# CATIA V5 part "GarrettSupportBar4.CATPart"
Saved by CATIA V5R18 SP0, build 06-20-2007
Part number: NLG-10020-1
Bounding box of the stored display mesh (mm): x -25.4 to 912.519, y -139.7 to 139.7, z -50.787 to 50.787
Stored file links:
  \\william7-64\echange\4Gavin\iPad\new.CATPart
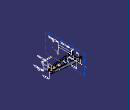
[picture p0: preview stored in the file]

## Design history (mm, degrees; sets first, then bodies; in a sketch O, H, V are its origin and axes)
AxisSystem1 "Absolute Axis System": origin (0, 0, 0), X (1, 0, 0), Y (0, 1, 0), Z (0, 0, 1)
TTRSSet1
f4a2d38f3ddc11d3a929006094b99c4b_11 "CATTPSSet"
Set1 "DATUM PLANES"
  Plane1 "DATUM A": type Offset, RefPlane start face of Pocket2, Offset 0, reversed
  Plane2 "DATUM B": type Offset, RefPlane face of Pad1 from Sketch1.L9, Offset 0, reversed
  Plane3 "DATUM C": type Offset, RefPlane face of Pad1 from Sketch1.L8, Offset 0, reversed
Body1 (main body)
  Sketch1 on face of AxisSystem1, origin (0, 0, 0), H (1, 0, 0), V (0, 1, 0)
    line L1 (912.9878, 76.2) -> (912.9878, 50.8)
    point P1 (912.9878, 76.2)
    point P2 (912.9878, -76.2)
    line L2 (-25.4, -139.7) -> (127, -139.7)
    point P3 (127, -139.7)
    line L3 (127, -139.7) -> (810.8024, -76.2543)
    line L4 (811.9757, -76.2) -> (912.9878, -76.2)
    point P4 (912.9878, 76.2)
    point P5 (811.3878, 76.2)
    line L5 (811.9757, 76.2) -> (912.9878, 76.2)
    point P6 (127, 139.7)
    line L6 (127.5854, 139.6457) -> (810.8024, 76.2543)
    point P7 (-25.4, 139.7)
    line L7 (-25.4, 139.7) -> (126.4121, 139.7)
    line L8 (-25.4, 114.3) -> (88.9, 114.3)
    line L9 (101.6, 101.6) -> (101.6, -101.6)
    line L10 (88.9, -114.3) -> (-25.4, -114.3)
    point P8 (101.6, 114.3)
    point P9 (101.6, -114.3)
    line L11 (-25.4, 139.7) -> (-25.4, 114.3)
    reference intersected line E1 through (0, 0) direction (-1, 0) from face of AxisSystem1
    line L12 (-25.4, -114.3) -> (-25.4, -139.7)
    line L13 (912.9878, 50.8) -> (849.4878, 50.8)
    line L14 (836.7878, 38.1) -> (836.7878, -38.1)
    line L15 (849.4878, -50.8) -> (912.9878, -50.8)
    line L16 (912.9878, -50.8) -> (912.9878, -76.2)
    arc A1 centre (811.9757, -88.9) radius 12.7 from (810.8024, -76.2543) to (811.9757, -76.2) cw
    arc A2 centre (811.9757, 88.9) radius 12.7 from (811.9757, 76.2) to (810.8024, 76.2543) cw
    arc A3 centre (126.4121, 127) radius 12.7 from (127.5854, 139.6457) to (126.4121, 139.7) ccw
    arc A4 centre (88.9, 101.6) radius 12.7 from (88.9, 114.3) to (101.6, 101.6) cw
    arc A5 centre (88.9, -101.6) radius 12.7 from (101.6, -101.6) to (88.9, -114.3) cw
    arc A6 centre (849.4878, 38.1) radius 12.7 from (849.4878, 50.8) to (836.7878, 38.1) ccw
    arc A7 centre (849.4878, -38.1) radius 12.7 from (836.7878, -38.1) to (849.4878, -50.8) ccw
    circle A8 centre (285.4046, 0) radius 73.668
    point P36 (285.4046, 0)
    circle A9 centre (469.199, 0) radius 56.6878
    point P37 (469.199, 0)
    point P38 (525.8868, 0)
    circle A10 centre (652.9934, 0) radius 39.7077
    point P39 (652.9934, 0)
    point P40 (692.7011, 0)
    distance P1 H = 76.2
    distance L10 L2 = 25.4
    distance E1 L7 = 139.7
    distance L11 L9 = 127
    distance P1 P2 = 152.4
    distance L13 L5 = 25.4
    distance L15 L4 = 25.4
    distance L1 L14 = 76.2
    radius A1 = 12.7
    distance P5 P4 = 101.6
    radius A2 = 12.7 {= Sketch1.radius(A1)}
    distance P7 P6 = 152.4
    radius A3 = 12.7 {= Sketch1.radius(A1)}
    distance P8 P9 = 228.6
    radius A4 = 12.7 {= Sketch1.radius(A1)}
    radius A5 = 12.7 {= Sketch1.radius(A1)}
    radius A6 = 12.7 {= Sketch1.radius(A1)}
    radius A7 = 12.7 {= Sketch1.radius(A1)}
    distance L9 L14 = 735.1878
    distance L14 P39 = 183.7944
    distance P39 P37 = 183.7944 {= Sketch1.distance(L14 P39)}
    distance P37 P36 = 183.7944 {= Sketch1.distance(L14 P39)}
    distance P36 L9 = 183.8046 (reference)
    distance A8 L6 = 50.8
    distance A9 L6 = 50.8
    distance A10 L6 = 50.8
    vertical: L1 V, L9 V, L11 V, L14 V
    horizontal: L2 H, L4 H, L8 H, L10 H, L13 H, L15 H
    symmetry: P2 P4 H, L4 L5 H, P3 P6 H, L3 L6 H, L2 L7 H
    coincidence: L11 L12, L1 L16, L5 P5, L6 P5, L6 P6, L7 P6, L8 P8, L9 P8, L9 P9, L10 P9, P36 H, P37 H, A9 P38, P38 H, P39 H, A10 P40, P40 H
    tangency: A1 L3, A1 L4, A2 L5, A2 L6, A3 L6, A3 L7, A4 L8, A4 L9, A5 L9, A5 L10, A6 L13, A6 L14, A7 L14, A7 L15
  Pad1: profile Sketch1, direction (0, 0, 1), length 50.8, mirrored extent
  Sketch2 on face of Pad1, origin (0, -139.7, 0), H (1, 0, 0), V (0, 0, 1)
    arc A1 centre (881.2378, 0) radius 31.75 from (881.9445, -31.7421) to (881.9445, 31.7421) ccw
    point P1 (881.2378, 0)
    arc A2 centre (25.4, 0) radius 50.8 from (26.5308, 50.7874) to (26.5308, -50.7874) ccw
    point P2 (25.4, 0)
    reference projected line E1 (912.9878, -50.8) -> (912.9878, 50.8) from edge [face of Pad1 | face of Pad1]
    reference projected line E2 (-25.4, -50.8) -> (-25.4, 50.8) from edge [face of Pad1 | face of Pad1]
    line L1 (26.5308, 50.7874) -> (881.9445, 31.7421)
    line L2 (881.9445, -31.7421) -> (26.5308, -50.7874)
    line L3 (-110, 130) -> (970, 130)
    line L4 (970, 130) -> (970, -130)
    line L5 (970, -130) -> (-110, -130)
    line L6 (-110, -130) -> (-110, 130)
    circle A3 centre (25.4, 0) radius 31.75
    circle A4 centre (881.2378, 0) radius 19.05
    radius A1 = 31.75
    radius A2 = 50.8
    radius A3 = 31.75
    radius A4 = 19.05
    coincidence: P1 H, P2 H
    tangency: A1 E1, A2 E2, L1 A2, L1 A1, L2 A1, L2 A2
    horizontal: L3 H, L5 H
    vertical: L4 V, L6 V
  Pocket1: profile Sketch2, direction (0, 1, 0), through (limit type 3)
  Sketch3 on face of AxisSystem1, origin (0, 0, 0), H (1, 0, 0), V (0, 1, 0)
    offset line E1 (140.8733, 112.9037) -> (799.8611, 51.7604) from edge [face of Pocket1 | face of Pad1]
    offset line E2 (811.3878, 39.1147) -> (811.3878, -39.1147) from edge [face of Pocket1 | face of Pad1]
    offset line E3 (140.8733, -112.9037) -> (799.8611, -51.7604) from edge [face of Pad1 | face of Pocket1]
    offset line E4 (127, -100.258) -> (127, 100.258) from edge [face of Pocket1 | face of Pad1]
    arc A1 centre (798.6878, 39.1147) radius 12.7 from (799.8611, 51.7604) to (811.3878, 39.1147) cw
    arc A2 centre (798.6878, -39.1147) radius 12.7 from (811.3878, -39.1147) to (799.8611, -51.7604) cw
    arc A3 centre (139.7, 100.258) radius 12.7 from (140.8733, 112.9037) to (127, 100.258) ccw
    arc A4 centre (139.7, -100.258) radius 12.7 from (140.8733, -112.9037) to (127, -100.258) cw
    radius A1 = 12.7
    radius A2 = 12.7
    radius A3 = 12.7
    radius A4 = 12.7
    tangency: A1 E1, A1 E2, A2 E2, A2 E3, A3 E1, A3 E4, A4 E3, A4 E4
  Pocket2: profile Sketch3, direction (0, 0, -1), through (limit type 3), opposite side length -6.35
  Sketch4 on face of AxisSystem1, origin (0, 0, 0), H (1, 0, 0), V (0, 1, 0)
    offset line E1 (140.8733, 112.9037) -> (799.8611, 51.7604) from edge [face of Pocket1 | face of Pad1]
    offset line E2 (811.3878, 39.1147) -> (811.3878, -39.1147) from edge [face of Pocket1 | face of Pad1]
    offset line E3 (140.8733, -112.9037) -> (799.8611, -51.7604) from edge [face of Pad1 | face of Pocket1]
    offset line E4 (127, -100.258) -> (127, 100.258) from edge [face of Pocket1 | face of Pad1]
    arc A1 centre (798.6878, 39.1147) radius 12.7 from (799.8611, 51.7604) to (811.3878, 39.1147) cw
    arc A2 centre (798.6878, -39.1147) radius 12.7 from (811.3878, -39.1147) to (799.8611, -51.7604) cw
    arc A3 centre (139.7, -100.258) radius 12.7 from (127, -100.258) to (140.8733, -112.9037) ccw
    arc A4 centre (139.7, 100.258) radius 12.7 from (127, 100.258) to (140.8733, 112.9037) cw
    radius A1 = 12.7
    radius A2 = 12.7
    radius A3 = 12.7
    radius A4 = 12.7
    tangency: A1 E1, A1 E2, A2 E2, A2 E3, A3 E4, A3 E3, A4 E4, A4 E1
  Pocket3: profile Sketch4, direction (0, 0, 1), through (limit type 3), opposite side length -6.35
  Fillet1: radius 3.175, on edge [face of Pocket3 from Sketch4.E4 | start face of Pocket3]
  Fillet2: radius 3.175, on edge [start face of Pocket2 | face of Pocket2 from Sketch3.E4]
  Sketch5 on start face of Pocket3, origin (785.5811, 30.7175, 6.35), H (1, 0, 0), V (0, 1, 0)
    point P1 (0, 0)
  Hole1: placed by Sketch5, at (785.5811, 30.7175, 6.35) direction (0, 0, -1), diameter 3.175, through (limit type 6)
  RectPattern1: of Hole1, direction 1 instances 4, spacing 19.05, along edge [face of Pocket3 from Sketch4.E2 | face of Pocket1 from Sketch2.L1], direction 2 instances 2, spacing 19.05, along edge [face of Pad1 from Sketch1.L5 | face of Pocket1 from Sketch2.L1]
